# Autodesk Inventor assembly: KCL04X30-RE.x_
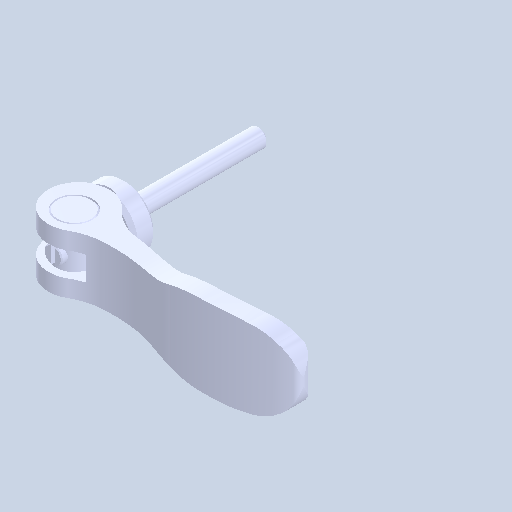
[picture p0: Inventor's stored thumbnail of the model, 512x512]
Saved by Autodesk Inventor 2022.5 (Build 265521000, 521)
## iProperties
Created: 2024-08
Part Number: KCL04X30-RE.x_
Document SubType Name: Assembly
Designer: ImaoCorp
Author: ImaoCorp
Sending System: SOLIDWORKS 2022-2022290
MC: AMD64
MC_MODEL: Intel64 Family 6 Model 60 Stepping 3, GenuineIntel
OS: Windows_NT
FRU: Parasolid Version 33.1, build 260,  4-25-2022
FORMAT: text
GUISE: transmit
KEY: FILEKCL04X30-RE.x_t
DATE: Thu Aug 29 10:48:02 2024
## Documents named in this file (5)
- Y:\5.更新分\2024年対応\1001_KCL\データ\kcl04x30-re\KCL04X30-RE.x_.iam
- Y:\5.更新分\2024年対応\1001_KCL\データ\kcl04x30-re\KCL4X30-RE_01.ipt
- Y:\5.更新分\2024年対応\1001_KCL\データ\kcl04x30-re\KCL4X30-RE_02.ipt
- Y:\5.更新分\2024年対応\1001_KCL\データ\kcl04x30-re\KCL4X30-RE_03.ipt
- Y:\5.更新分\2024年対応\1001_KCL\データ\kcl04x30-re\KCL4X30-RE_04.ipt
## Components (4 placed, 4 different names)
1. KCL4X30-RE_01
2. KCL4X30-RE_02
3. KCL4X30-RE_03
4. KCL4X30-RE_04
